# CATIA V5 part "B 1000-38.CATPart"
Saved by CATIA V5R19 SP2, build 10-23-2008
Part number: B 1000-38
Bounding box of the stored display mesh (mm): x -24.865 to 24.865, y -24.997 to 24.997, z 0 to 171
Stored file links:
  C:\Users\Bora\Desktop\3D Katı model\B serisi\B 1000\B 1000-38.CATPart
  C:\Program Files\Dassault Systemes\B19\intel_a\reffiles\standard\MetricThickPitch.txt
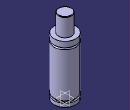
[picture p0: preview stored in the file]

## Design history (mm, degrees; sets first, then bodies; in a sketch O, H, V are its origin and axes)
Body1 (main body)
  Sketch1 on yz-plane, origin (0, 0, 0), H (0, 1, 0), V (0, 0, 1)
    point P3 (15, 170)
    point P5 (15, 170)
    point P10 (25, 113.5)
    point P11 (25, 117.5)
    point P13 (25, 117.5)
    point P14 (25, 113.5)
    line L1 (25, 0) -> (25, 8)
    line L2 (15, 170) -> (15, 130)
    arc A1 centre (14, 170) radius 1 from (15, 170) to (14, 171) ccw
    line L3 (21.5, 13) -> (21.5, 8)
    line L4 (25, 13) -> (25, 113.5)
    line L5 (25, 117.5) -> (25, 130)
    arc A2 centre (25, 115.5) radius 2 from (25, 117.5) to (25, 113.5) ccw
    line L6 (14, 171) -> (0, 171)
    point P15 (0, 171)
    line L7 (15, 130) -> (25, 130)
    line L8 (0, 0) -> (25, 0)
    line L9 (21.5, 13) -> (25, 13)
    line L10 (21.5, 8) -> (25, 8)
    coincidence: P15 V, P3 P5, P10 P14, P11 P13
    tangency: L6 A1
    horizontal: L7 H, L8 H, L9 H, L10 H
  Shaft1: profile Sketch1, axis Sketch1.V, angle 360
  Sketch2 on face of Shaft1 from Sketch1.L8, origin (0, 0, 0), H (1, 0, 0), V (0, -1, 0)
    point P1 (10, 0)
    distance P1 V = 10
  Hole1: placed by Sketch2, at (10, 0, 0) direction (0, 0, 1), diameter 6.647, depth 13, threaded "M8", thread diameter 8, thread depth 13, pitch 1.25
  CircPattern1: of Hole1, instances 2, angular step 180, axis from xy-plane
